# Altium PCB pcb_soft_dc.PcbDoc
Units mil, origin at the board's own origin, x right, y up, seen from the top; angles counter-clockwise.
Board outline 1980 x 895 mil, 2 copper layers (Top Layer, Bottom Layer); 21 components, 12 nets, 53 pads, 0 vias.
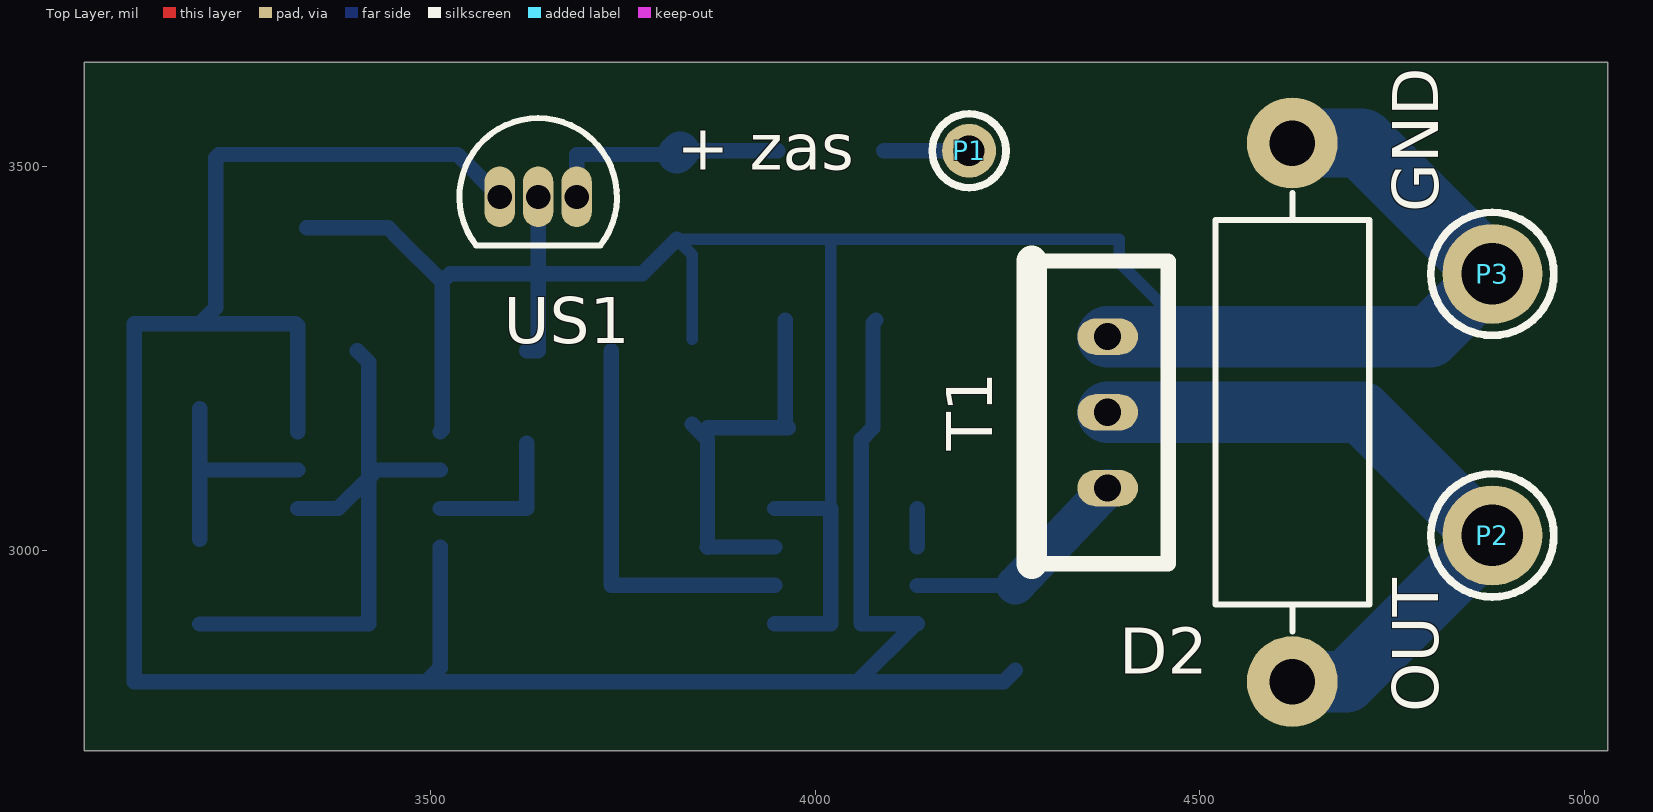
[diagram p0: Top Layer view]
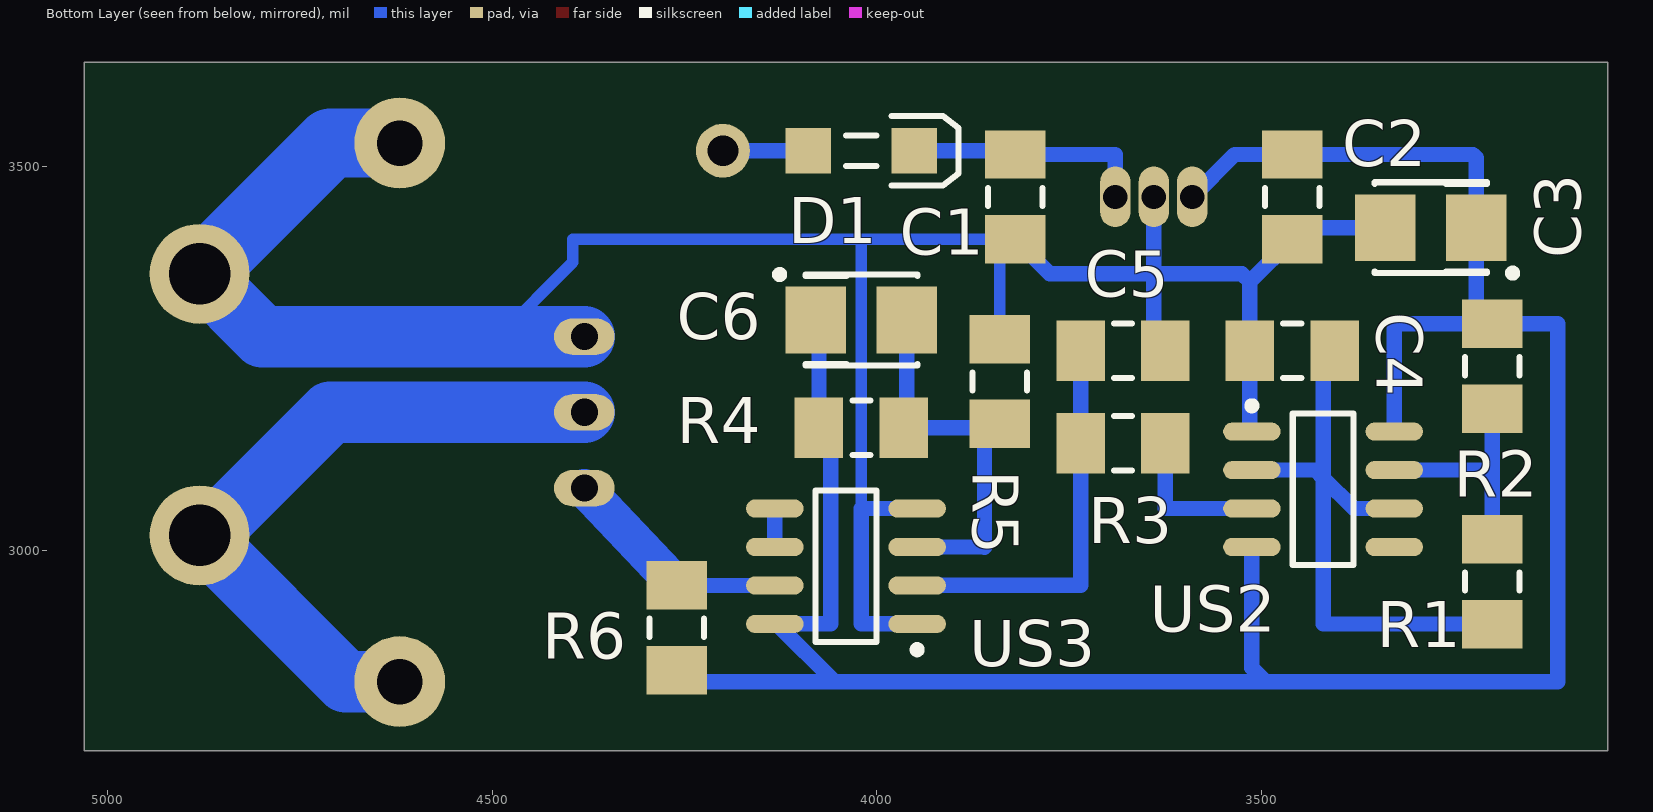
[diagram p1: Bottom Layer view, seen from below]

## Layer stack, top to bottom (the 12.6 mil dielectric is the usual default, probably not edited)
Top Layer: signal copper 1.4
Dielectric: dielectric 12.6, FR-4, Dk 4.8
Bottom Layer: signal copper 1.4

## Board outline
3050,2740 3050,3635 5030,3635 5030,2740

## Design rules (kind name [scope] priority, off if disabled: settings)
Clearance [All] p1: gap=10
PolygonConnect [All] p1: connectstyle=Relief reliefconductorwidth=10 reliefentries=4 polygonreliefangle="90 Angle"
RoutingVias [All] p1: holewidth=28 width=50 viastyle="Through Hole" minholewidth=28 minwidth=50 maxholewidth=28 maxwidth=50
SilkscreenOverComponentPads [All] p1: minsilkscreentomaskgap=10
SolderMaskExpansion [All] p1: expansion=4
Width [All] p1: maxlimit=200 minlimit=15 preferedwidth=20
27 further rules are at their usual default settings.

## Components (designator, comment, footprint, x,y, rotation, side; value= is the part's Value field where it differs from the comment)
C1 "100n" MELF-1206 3820,3460 r90 bottom
C2 "100n" MELF-1206 3460,3460 r90 bottom
C3 "22u/16V B" "Tantal B 3528-1411" 3280,3420 r0 bottom
C4 "100n" MELF-1206 3460,3260 r180 bottom
C5 "100n" MELF-1206 3680,3260 r0 bottom
C6 "22u/16V B" "Tantal B 3528-1411" 4020,3300 r180 bottom
D1 "1N4148" "dioda MINIMELF" 4020,3520 r180 bottom
D2 "51V" "dioda 17,5mm dwukier" 4620,3180 r270 top
P1 "+ zas" "pad fi 1mm" 4200,3520 r0 top
P2 "wyjście" "pad fi 2mm" 4880,3020 r0 top
P3 "GND" "pad fi 2mm" 4880,3360 r0 top
R1 "820" MELF-1206 3200,2960 r90 bottom
R2 "4,7k" MELF-1206 3200,3240 r90 bottom
R3 "2,2k" MELF-1206 3680,3140 r180 bottom
R4 "330k" MELF-1206 4020,3160 r0 bottom
R5 "330k" MELF-1206 3840,3220 r270 bottom
R6 "2,2k" MELF-1206 4260,2900 r270 bottom
T1 "IRF3205" TO-220 4380,3180 r0 top
US1 "78L09" LP03 3640,3460 r270 top
US2 "NE555" D008_L 3420,3080 r180 bottom
US3 "LM311" D008_L 4040,2980 r0 bottom

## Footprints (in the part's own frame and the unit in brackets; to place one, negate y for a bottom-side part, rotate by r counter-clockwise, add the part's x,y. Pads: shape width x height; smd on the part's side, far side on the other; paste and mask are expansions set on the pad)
D008_L [mm] "SOIC, 8-Leads, Body 4.9x3.9mm, Pitch 1.27mm, IPC High Density"
  oval 1.9x0.6 smd: 1(-2.35,1.905) 2(-2.35,0.635) 3(-2.35,-0.635) 4(-2.35,-1.905) 5(2.35,-1.905) 6(2.35,-0.635) 7(2.35,0.635) 8(2.35,1.905)
  silkscreen extent -2.48,-2.5 1,2.88, body extent -1.95,-2.45 1.95,2.45, height 1.75
"dioda 17,5mm dwukier" [mm]
  round 3 hole 1.5: 1(-8.89,0) 2(8.89,0)
  silkscreen extent -7.24,-2.54 7.24,2.54, body extent -6.35,-2.54 6.35,2.54, height 5.08
"dioda MINIMELF" [mm] "SMT LED; 2 Flat Leads"
  rect 1.5x1.5 smd: 1(-1.75,0) 2(1.75,0)
  silkscreen extent -0.5,-1.15 3.2,1.15
LP03 [mm] "TO, Flat Index; 3 In-Line, Axial Leads; Body Dia. 4.8mm; Leads 0.56 x 0.41 mm (max)"
  oval 2x1 hole 0.8: 1(0,-1.27) 2(0,0) 3(0,1.27)
  silkscreen extent -2.6,-2.6 1.6,2.6
MELF-1206 [mm] "Metal Electrode Face (MELF) Resistor; Body 3.2 x 1.8 mm (LxDia)"
  rect 1.6x2 smd: 1(-1.4,0) 2(1.4,0)
  silkscreen extent -0.3,-0.9 0.3,0.9, body extent -2.3,-1.1 2.3,1.1, height 1.85
"pad fi 1mm" [mil]
  round 70 hole 40: 1(0,0)
  silkscreen extent -48,-48 48,48
"pad fi 2mm" [mil]
  round 130 hole 80: 1(0,0)
  silkscreen extent -80,-80 80,80
"Tantal B 3528-1411" [mm] "Capacitor, SM Tantalum; Body 3.5 x 2.8 mm (LxW typ)"
  rect 2x2.2 smd: 1(-1.5,0) 2(1.5,0)
  silkscreen extent -2.82,-1.5 1.85,1.62, body extent -2.6,-1.2 2.6,1.2, height 2.5
TO-220 [mm]
  oval 2x1.2 hole 0.9: 1(0,-2.5) 2(0,0) 3(0,2.5)
  silkscreen extent -2.5,-5 2,5

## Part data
C1 C2 C4 C5: library part kondensator
C3 C6: library part "kond biegunowy", "Polarized Capacitor"
D1: library part Diode, "Default Diode"
D2: library part "Transil dwukierunkowy"
P1 P2 P3: library part Pad, "Pad"
R1 R2 R3 R4 R5 R6: library part rezystor
T1: library part "MOSFET N"
US1: library part µA78L09ACLP, "Positive-Voltage Regulator"
US2: library part NE555D, "Precision Timer"
US3: library part PM211S, "Precision Voltage Comparator"

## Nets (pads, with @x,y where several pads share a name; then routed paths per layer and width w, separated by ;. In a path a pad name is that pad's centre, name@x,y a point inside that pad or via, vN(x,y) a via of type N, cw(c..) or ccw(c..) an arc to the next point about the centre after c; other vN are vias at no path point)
GND: C1.1 C2.1 C3.2 C4.1 C5.1 D2.1 P3.1 R5.1 T1.3 US1.2 US2.1 US3.1 US3.4 | length 3332.7
  Bottom Layer w15: R5.1 3840,3384.88 C1.1 4020,3404.88 ; 4020,3055 4020,3404.88 ; 4495,3278.43 4491.57,3278.43 4395,3375 4395,3405 4020,3405 4020,3404.88
  Bottom Layer w20: C3.2 3444.88,3420 C2.1 3515.12,3349.76 ; US2.1 3515.12,3157.6 C4.1 3515.12,3349.76 ; C5.1 3640,3260 3640,3360 ; US1.2 3640,3360 ; C1.1 3775.12,3360 3640,3360 ; US3.1 4020,2905 4020,3055 US3.4 ; 3515.12,3349.76 3525.35,3360 3640,3360
  Bottom Layer w80: T1.3 4491.57,3278.43 ; 4495,3278.43 4798.43,3278.43 P3.1
  Bottom Layer w90: D2.1 4710,3530 P3.1
NetC1_2: C1.2 D1.2 US1.3 | length 318.2
  Bottom Layer w20: US1.3 3690,3515 3690.12,3515.12 C1.2 ; C1.2@3824.88,3520 D1.2
  Bottom Layer w50: C1.2 C1.2@3824.88,3520
NetC2_2: C2.2 C3.1 C6.1 R2.2 R4.2 R6.2 US1.1 US2.4 US2.8 US3.8 | length 3349
  Bottom Layer w20: US2.8 3327.48,3292.52 3324.88,3295.12 R2.2 ; US2.4 3512.52,2847.76 3494.88,2830.12 ; US1.1 3534.88,3515.12 C2.2 3225.12,3515.12 3220.94,3510.94 C3.1 3220.94,3316.06 R2.2 ; C6.1 4075.12,3296.06 R4.2 4060,3144.88 4060,2905 US3.8@4130,2905 ; US3.8 US3.8@4130,2905 ; R6.2 4245.24,2830.12 4055.12,2830.12 ; R2.2 3114.88,3295.12 3114.88,2830.12 3494.88,2830.12 ; 3494.88,2830.12 4055.12,2830.12 ; 4055.12,2830.12 US3.8@4130,2905
NetC4_2: C4.2 R1.1 US2.2 US2.6 | length 787
  Bottom Layer w20: R1.1 3419.88,2904.88 3419.88,3094.88 ; US2.6 3380,3055 3419.88,3094.88 ; C4.2 3419.88,3245 3419.88,3094.88 ; US2.2 3430,3105 3419.88,3094.88
NetC5_2: C5.2 R3.1 US3.2 | length 517.3
  Bottom Layer w20: C5.2 R3.1 3735.12,2955.12 3947.36,2955.12 US3.2
NetC6_2: C6.2 R4.1 R5.2 US3.3 | length 502.6
  Bottom Layer w20: R5.2 3860,3144.88 3860,3005 ; R5.2@3860,3160 R4.1 3960.94,3163.94 C6.2 ; US3.3 3860,3005 ; 3860,3005 3859.88,3005 3860,3004.88 3860,3005
NetD1_1: D1.1 P1.1 | length 111.1
  Bottom Layer w20: D1.1 P1.1
NetD2_2: D2.2 P2.1 T1.2 | length 909.1
  Bottom Layer w80: T1.2 4710,3180 P2.1@4875,3015 ; D2.2 4690,2830 P2.1@4875,3015 ; P2.1@4880,3010 P2.1@4875,3015 ; P2.1 P2.1@4875,3015
NetR1_2: R1.2 R2.1 US2.7 | length 297.2
  Bottom Layer w20: R1.2 3200,3105 ; R2.1 3200,3105 ; US2.7 3200,3105
NetR3_2: R3.2 US2.3 | length 197.5
  Bottom Layer w20: US2.3 3625,3055 3624.88,3055.12 R3.2
NetR6_1: R6.1 T1.1 US3.7 | length 476
  Bottom Layer w20: US3.7 R6.1@4259.88,2955
  Bottom Layer w50: R6.1 T1.1 R6.1
NetUS3_5: US3.5 US3.6 | length 50
  Bottom Layer w20: US3.6 US3.5
pads on no net: US2.5

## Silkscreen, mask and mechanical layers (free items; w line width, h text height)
Top Overlay:
  text "+ zas" at 3820,3495 h60
  text "GND" at 4810,3440 h60 r90
  text "OUT" at 4810,2790 h60 r90
Mechanical 1:
  the board outline again, w10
